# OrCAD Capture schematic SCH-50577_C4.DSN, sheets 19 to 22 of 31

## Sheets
19 21 USB: size C
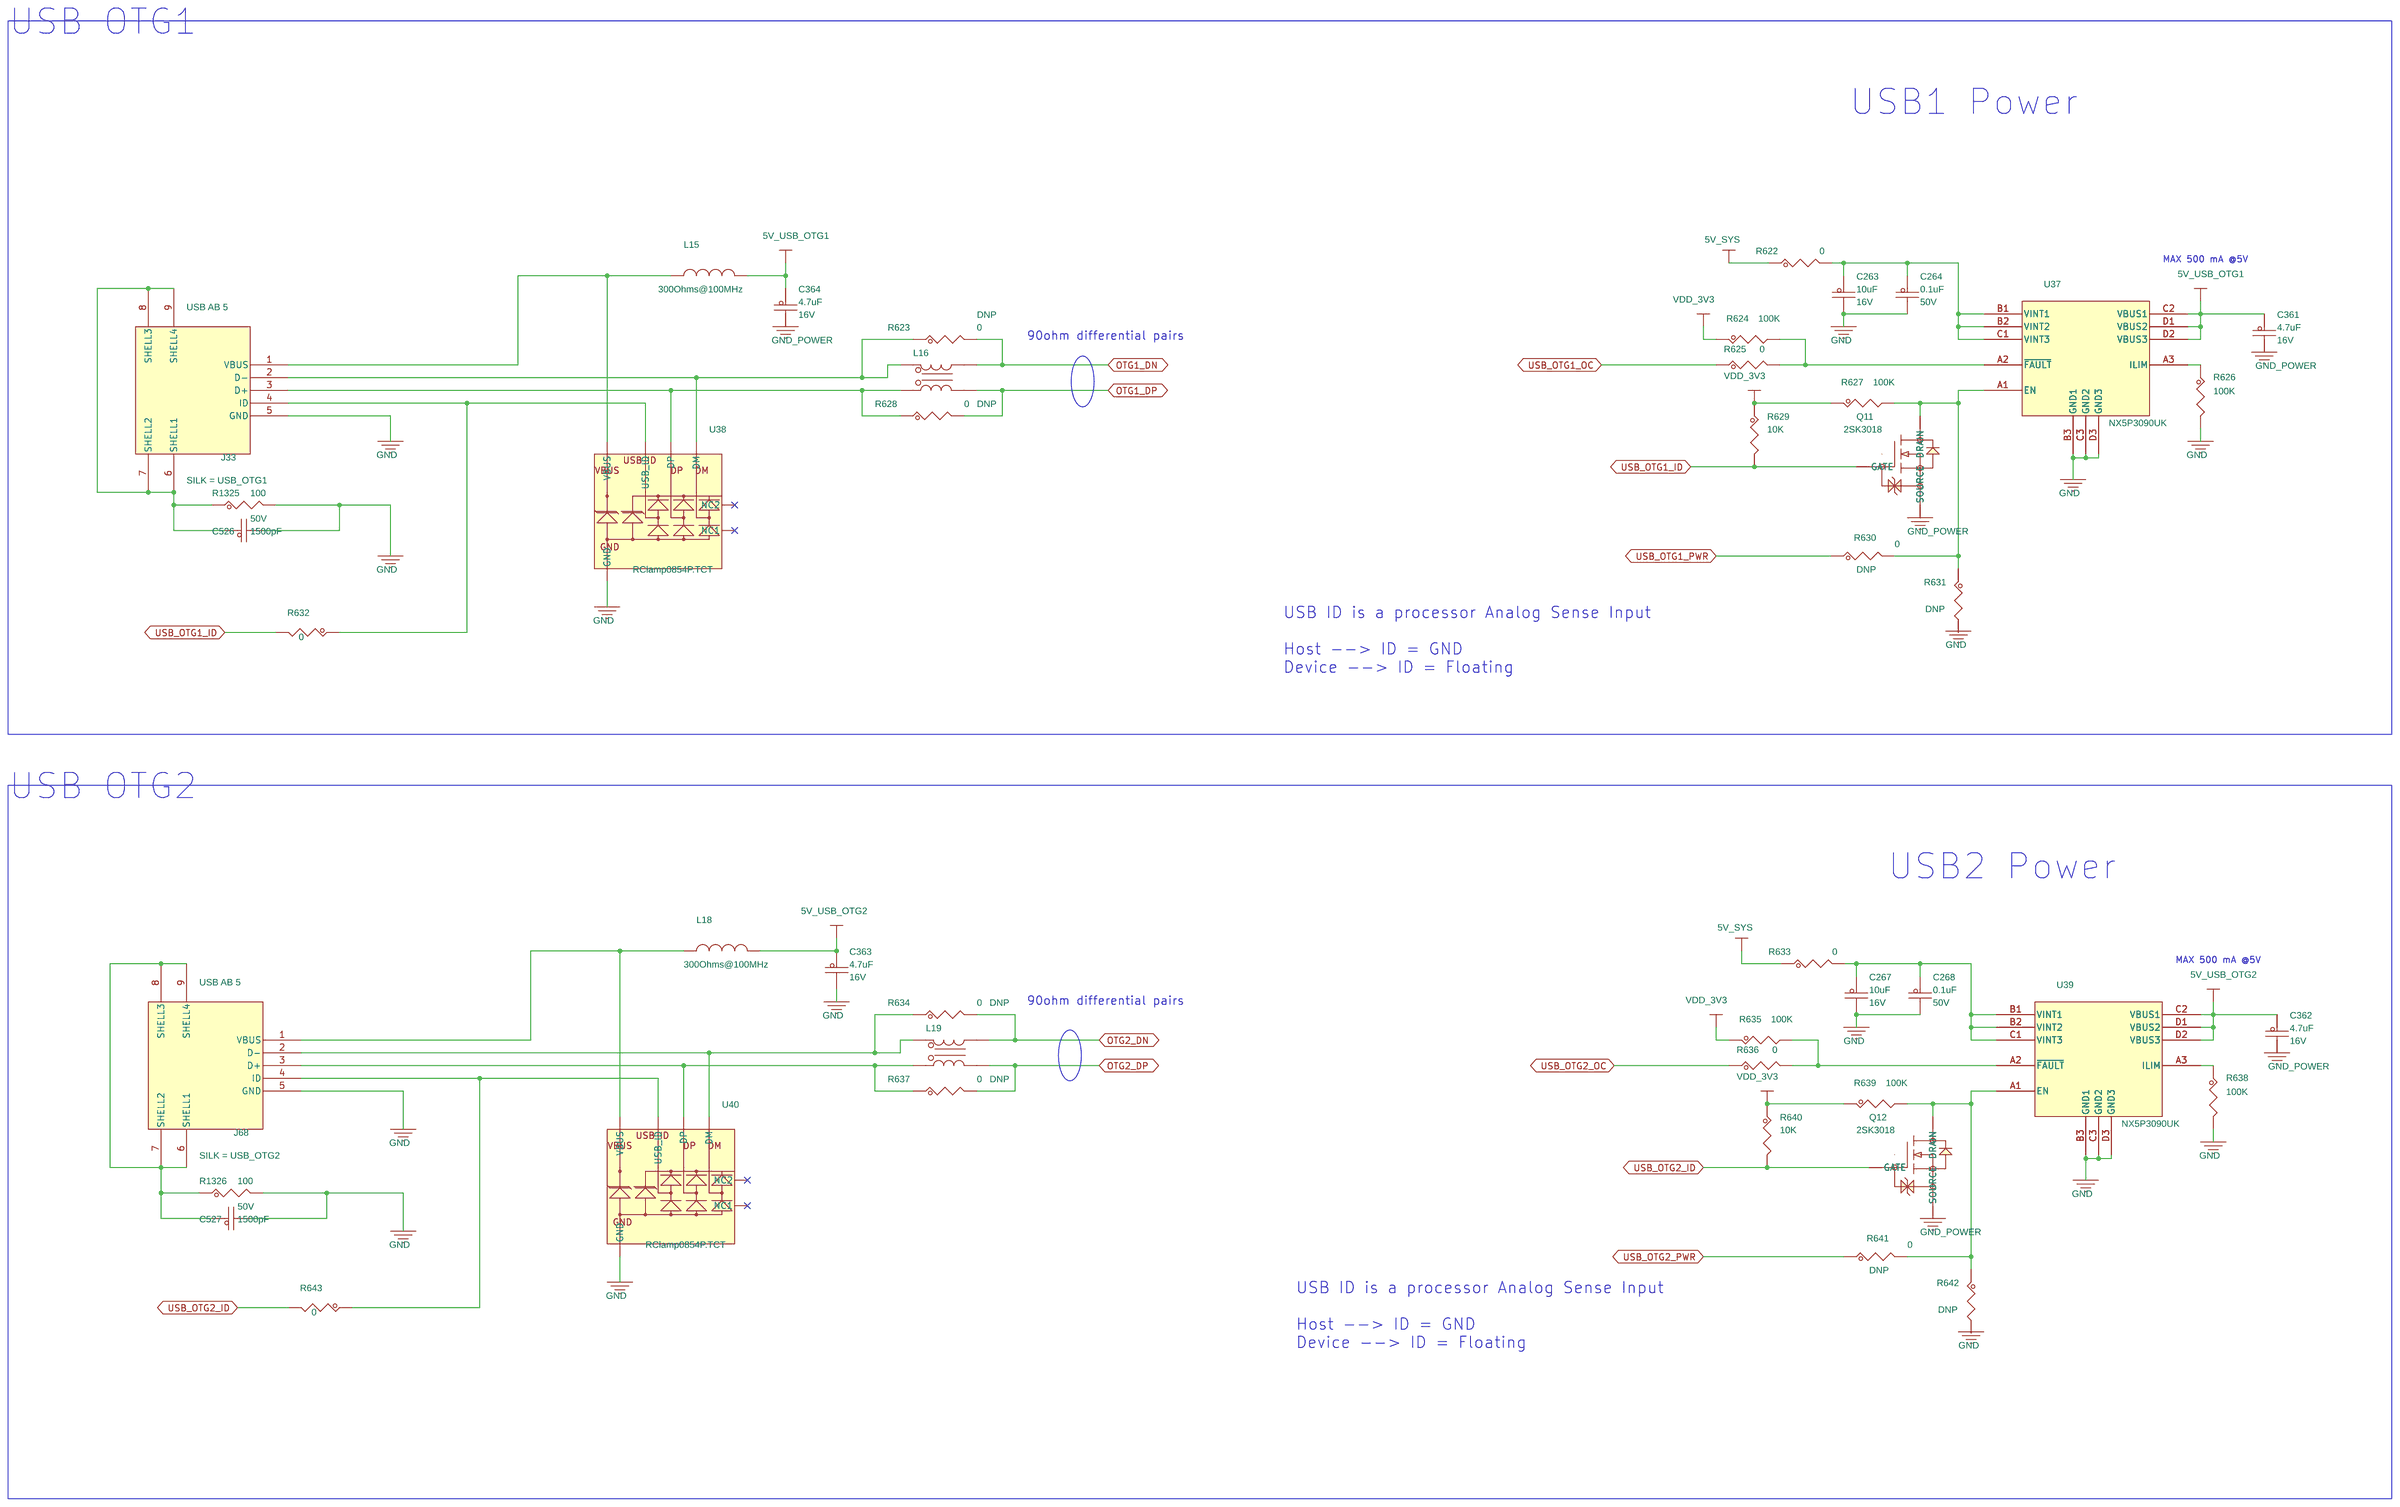
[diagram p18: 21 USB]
20 22 CAN: size C
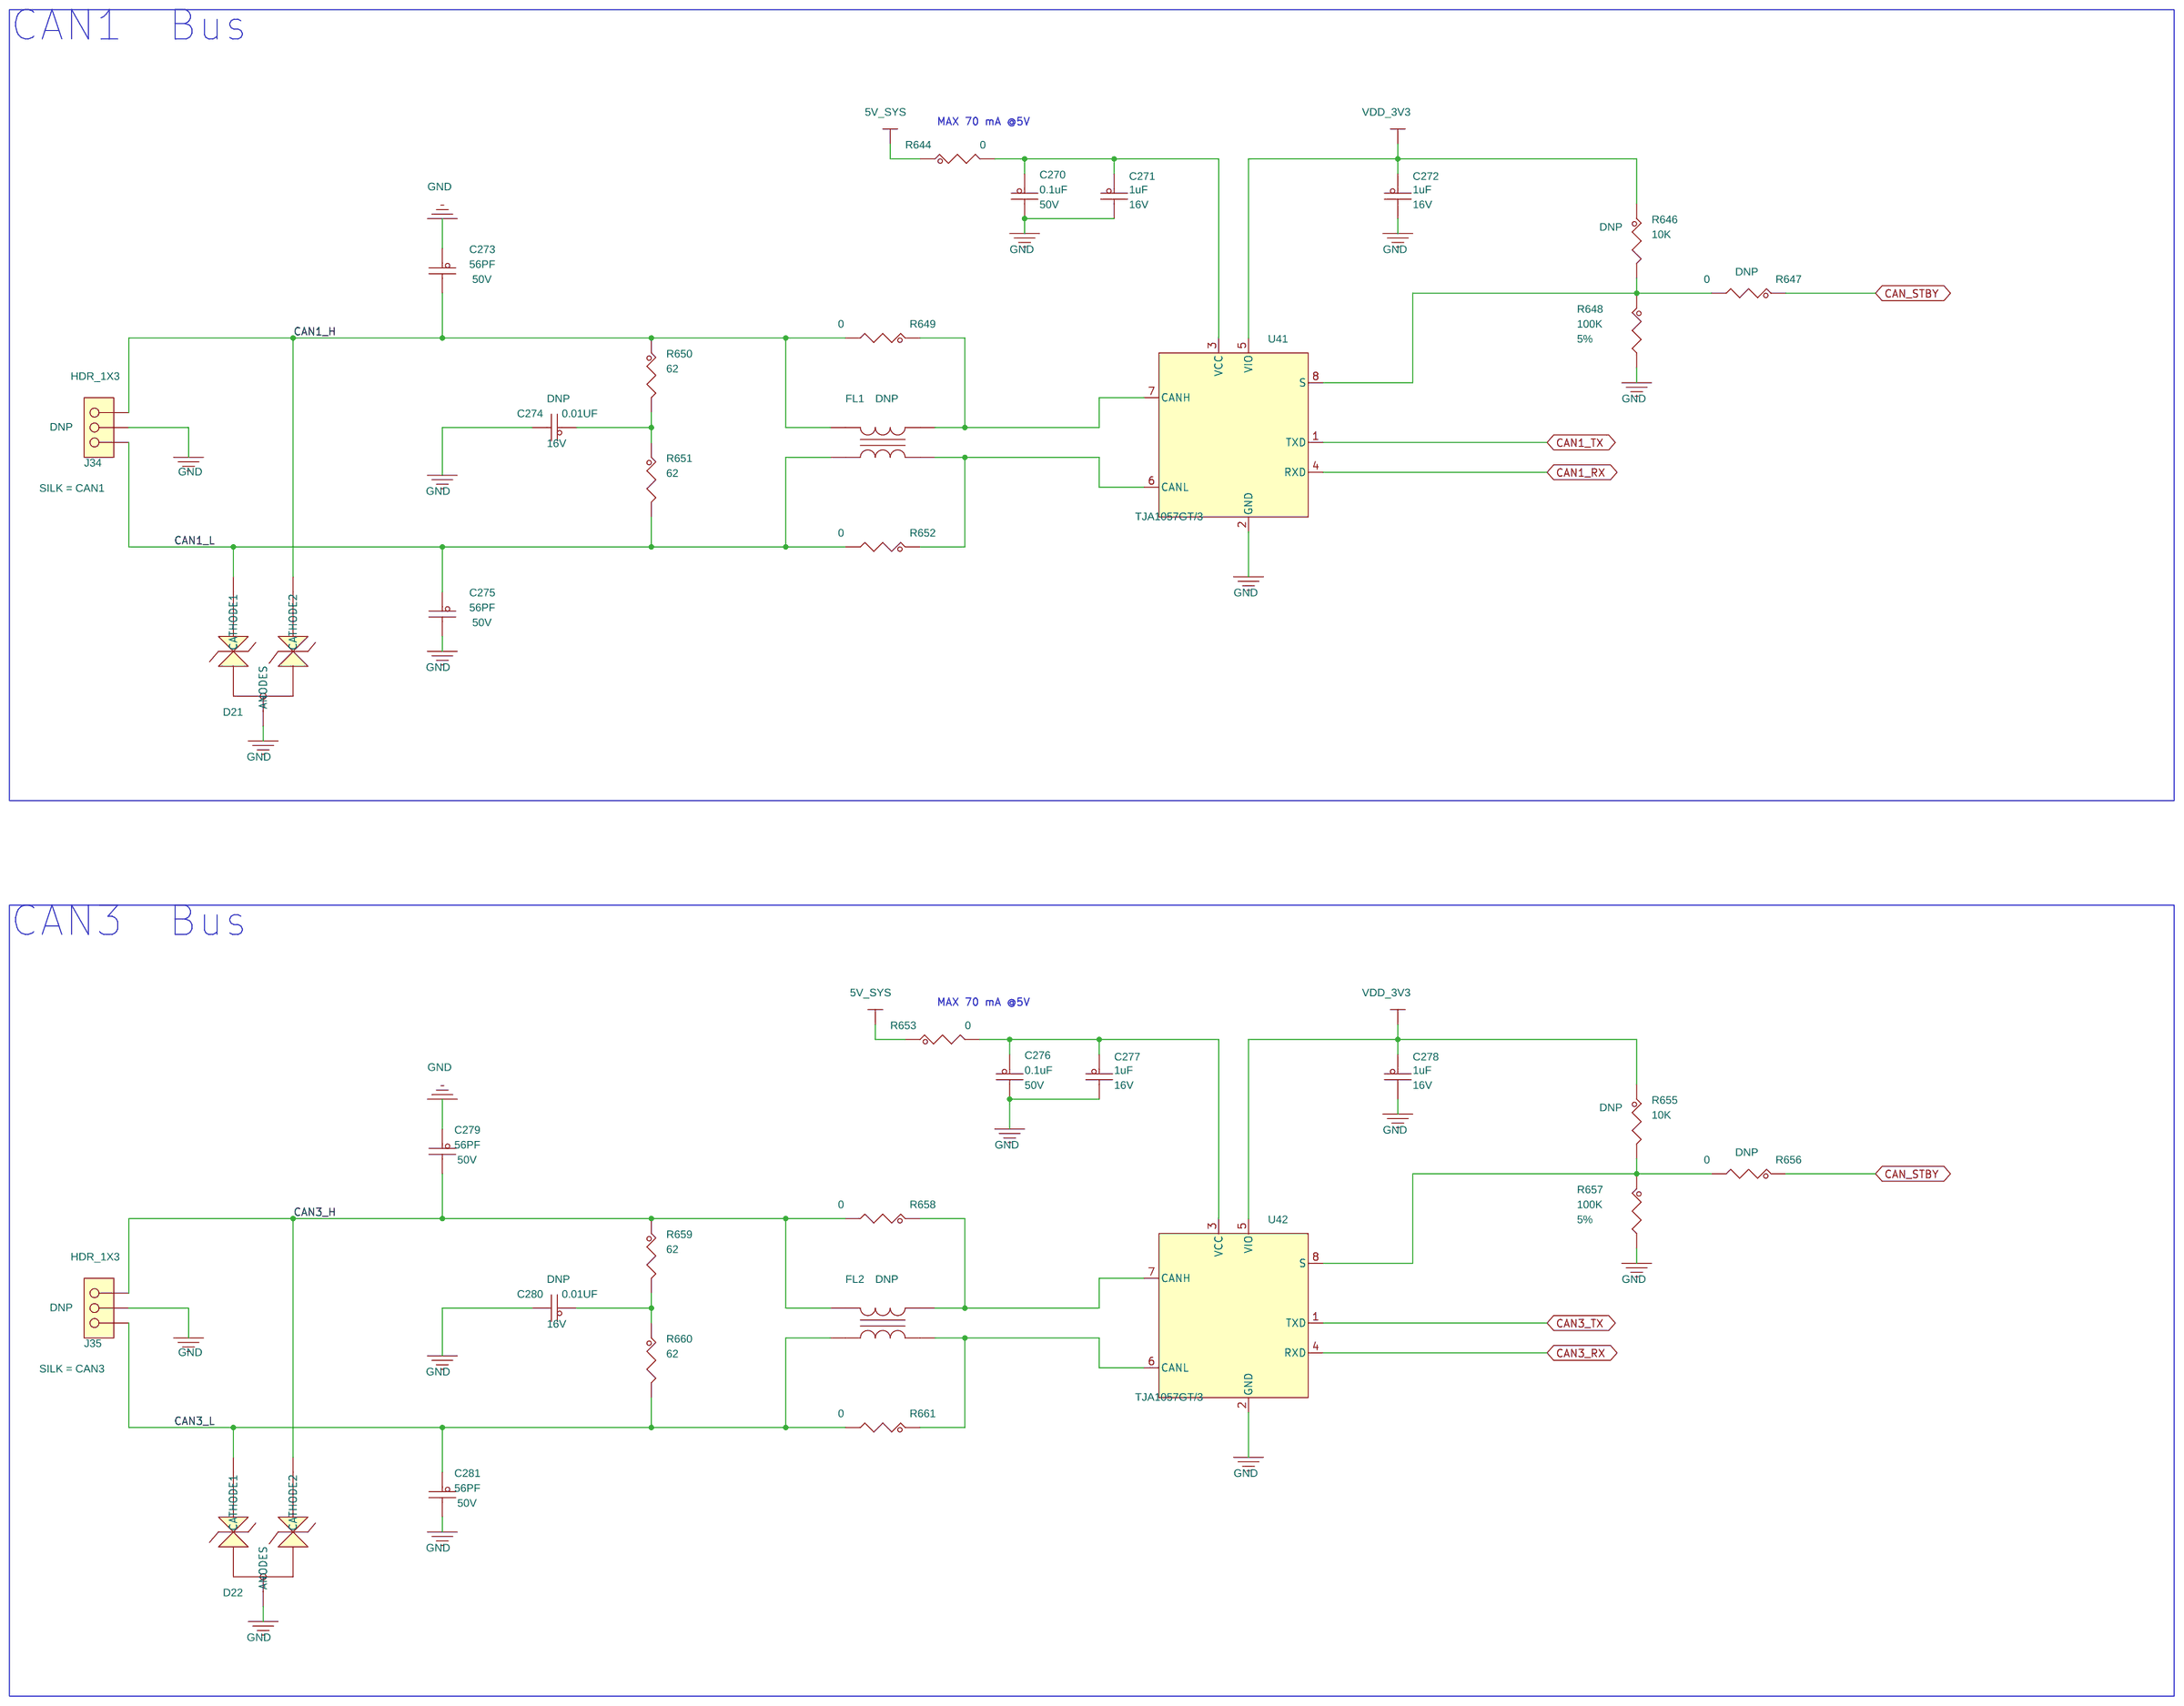
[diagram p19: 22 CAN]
21 23 M.2 Socket: size C
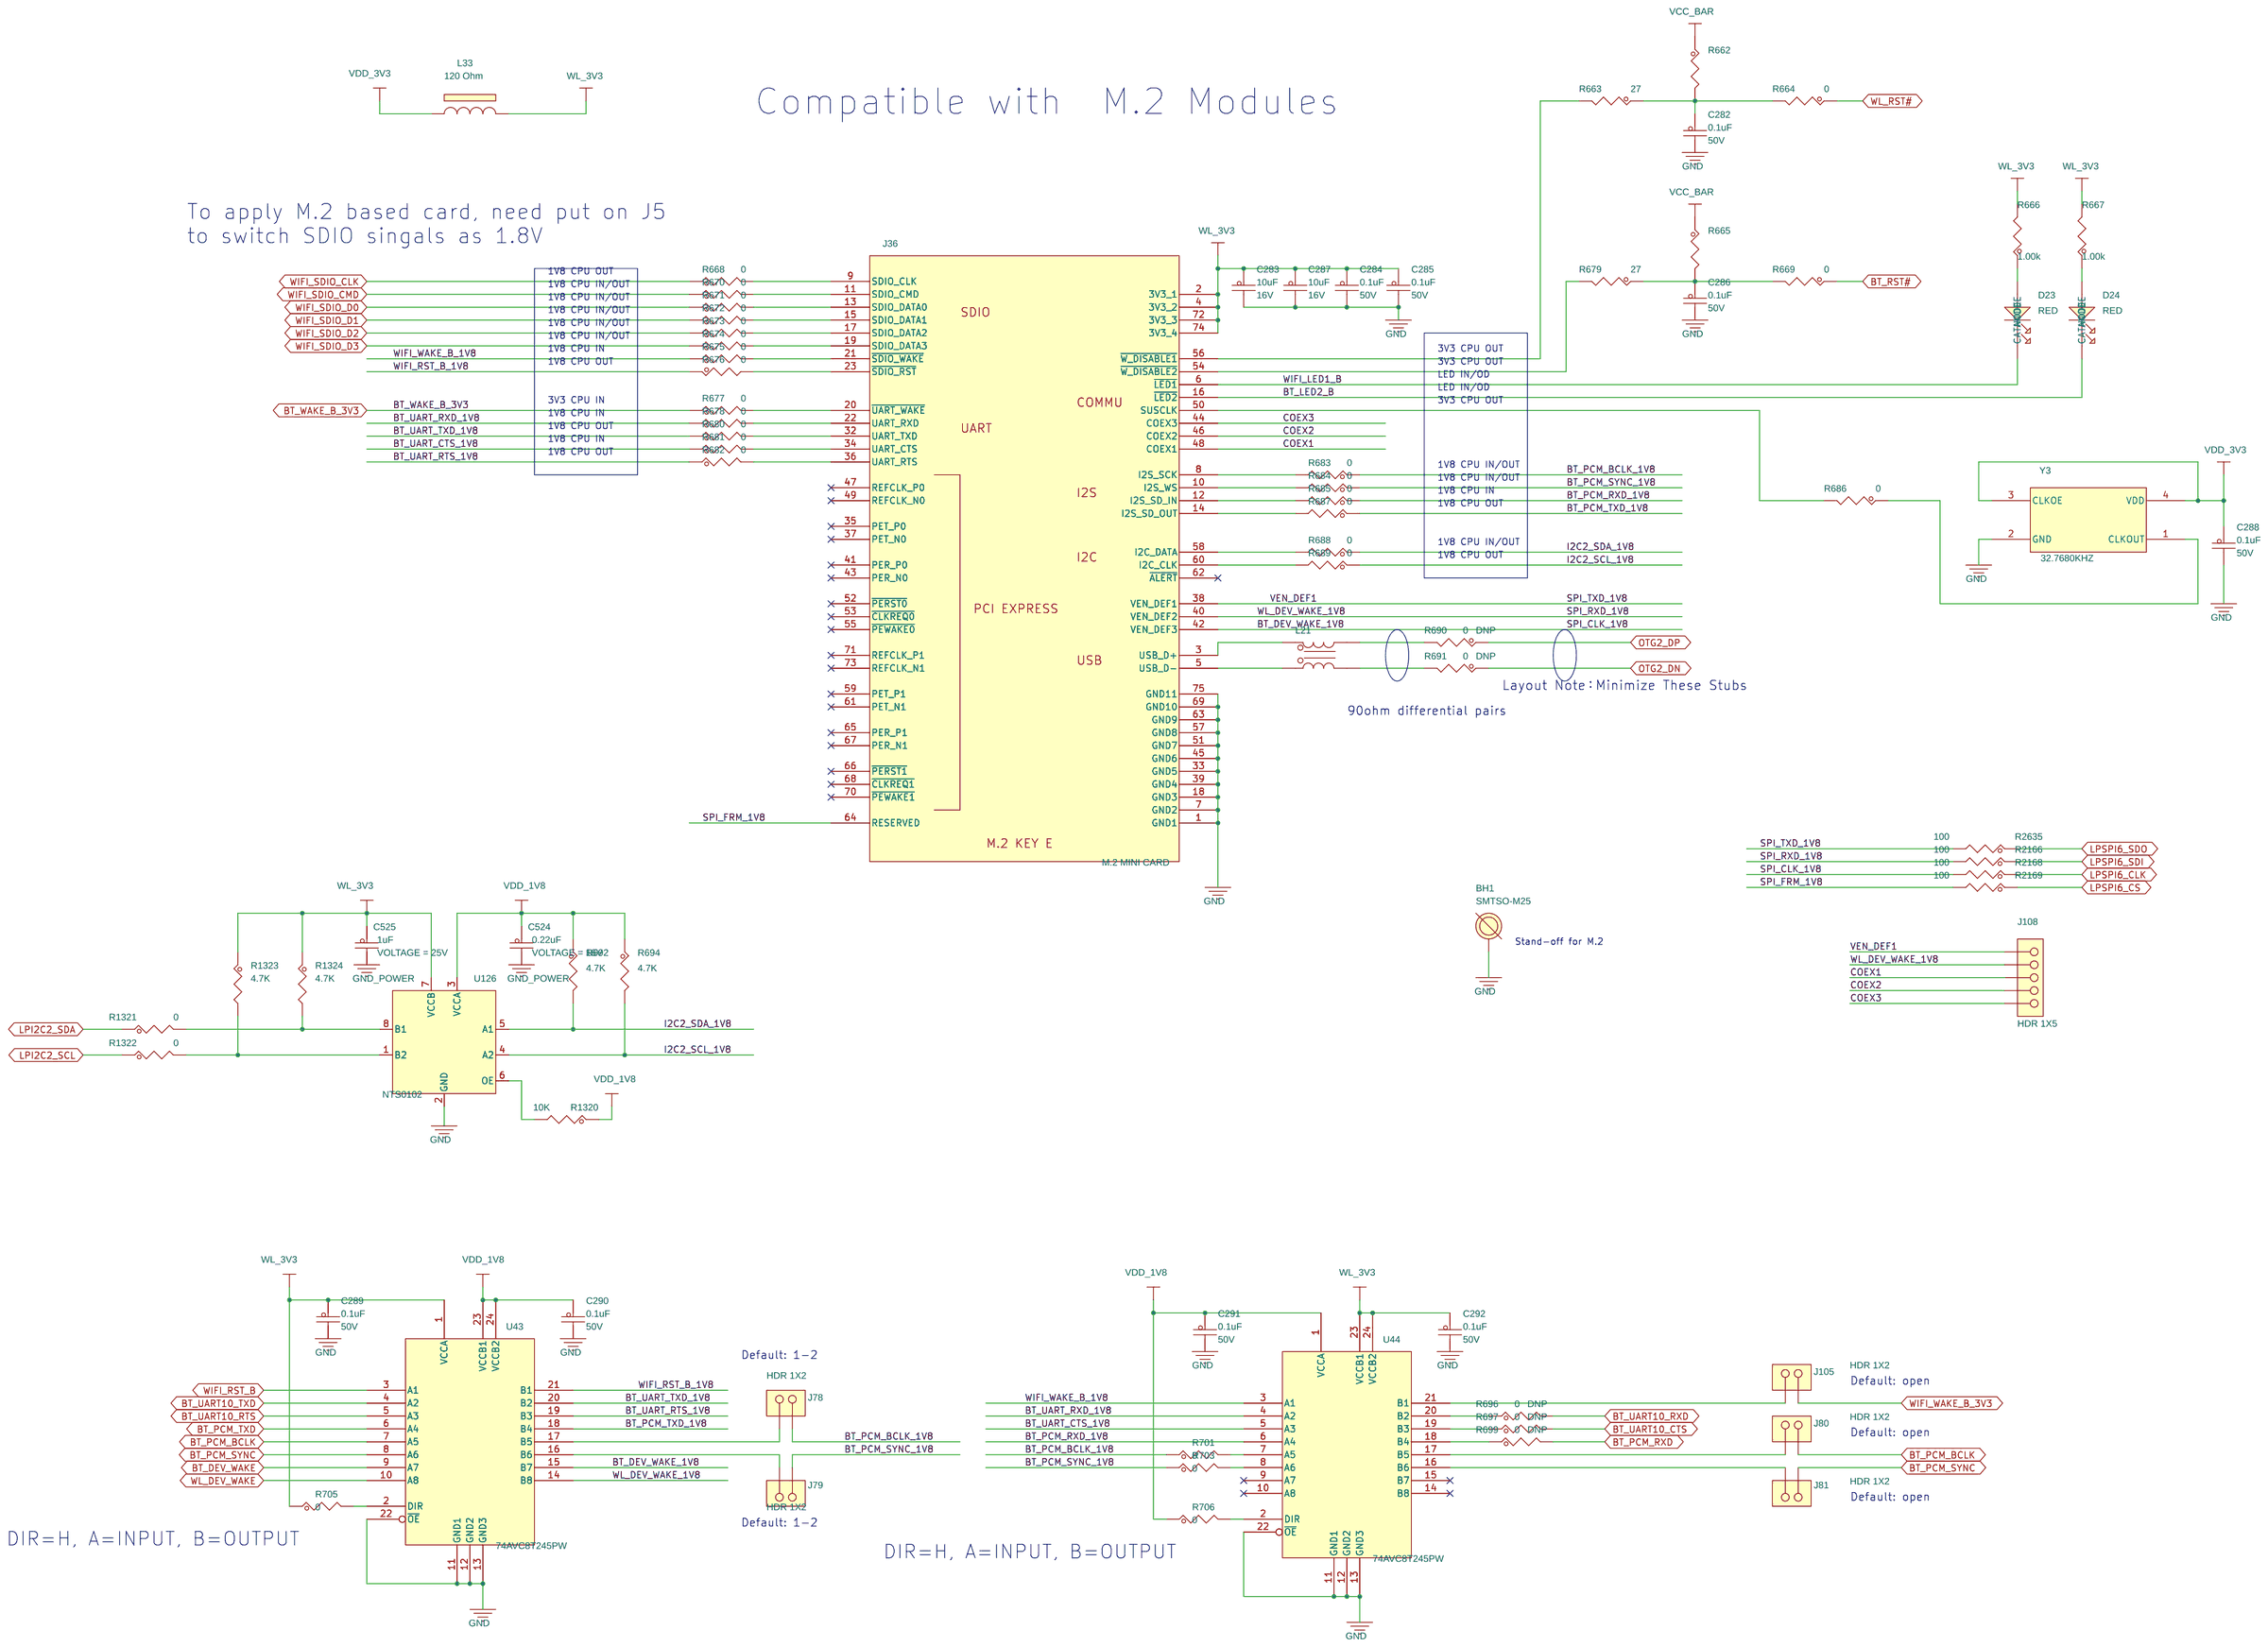
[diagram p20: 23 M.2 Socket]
22 24 Boot: size C
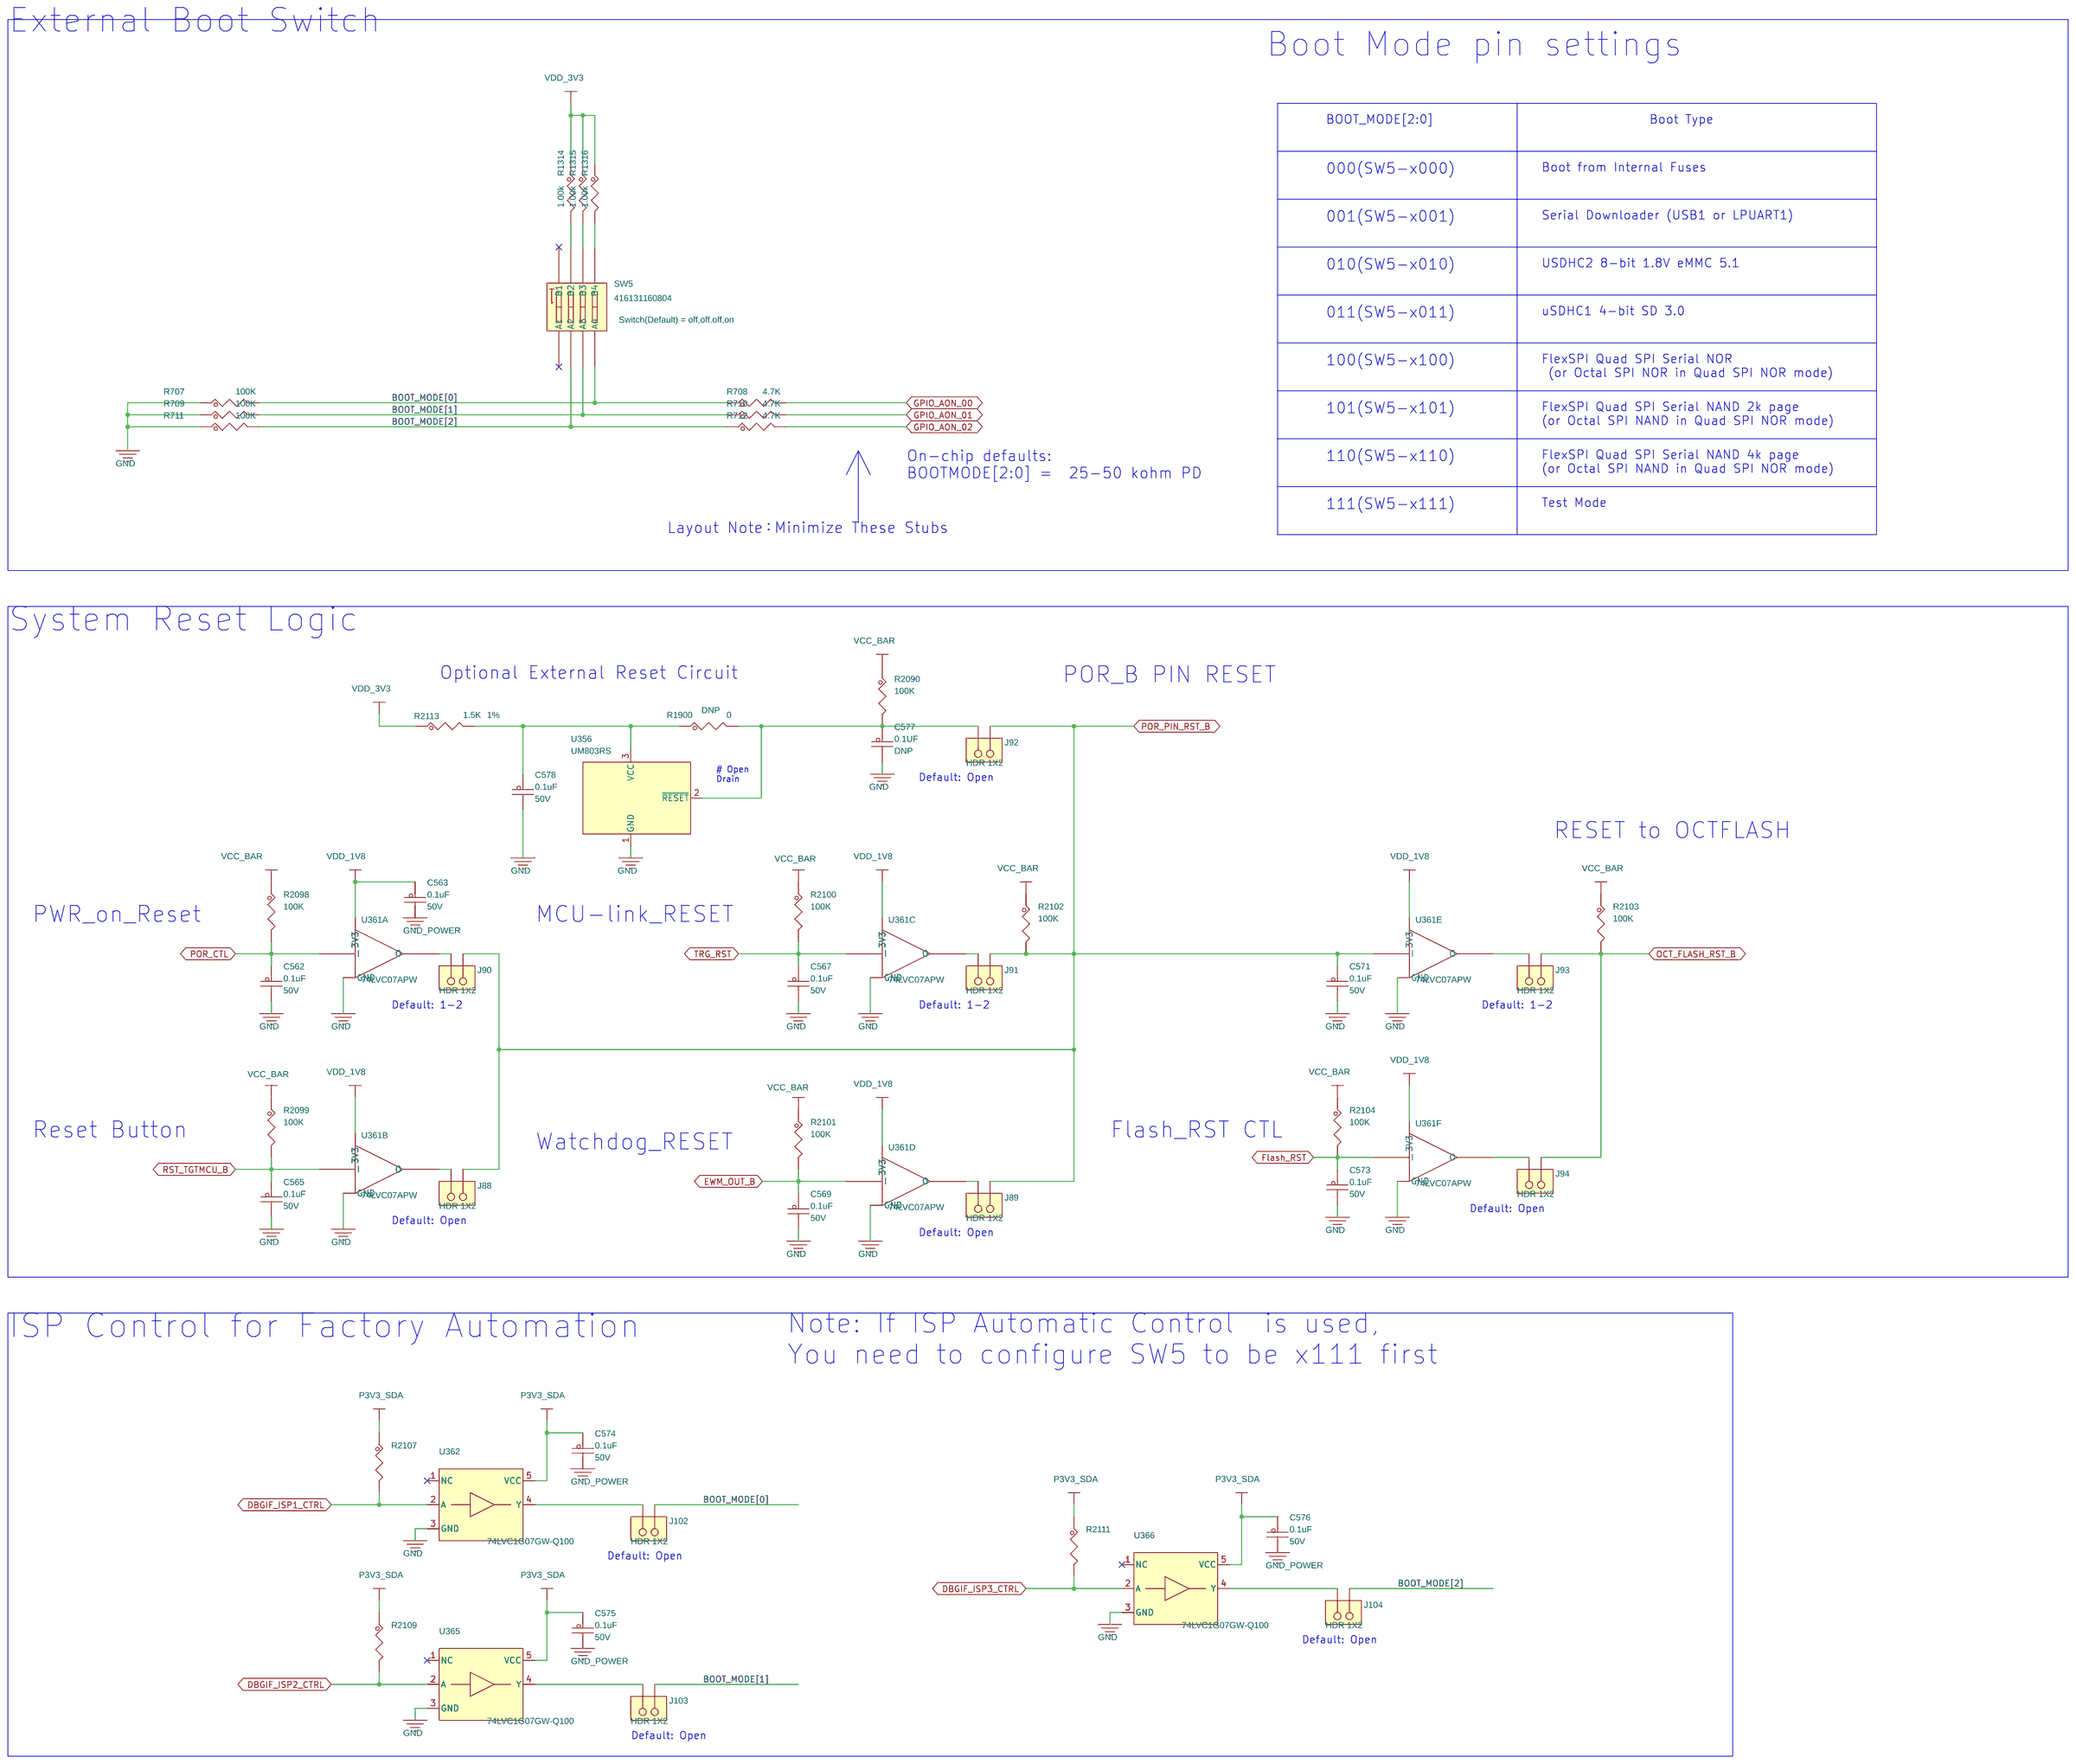
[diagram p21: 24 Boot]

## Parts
sheet 21 USB
C263  10uF  [CC0603_OV]
C264  0.1uF  [0402_CC]
C267  10uF  [CC0603_OV]
C268  0.1uF  [0402_CC]
C361  4.7uF  [CC0603_OV]
C362  4.7uF  [CC0603_OV]
C363  4.7uF  [CC0603_OV]
C364  4.7uF  [CC0603_OV]
C526  1500pF  [0402_CC]
C527  1500pF  [0402_CC]
J33  USB AB 5  [con9_microAB_usb_shell_th]
J68  USB AB 5  [con9_microAB_usb_shell_th]
L15  300Ohms@100MHz  [ind_1p8x1mm_sm]
L16  90OHM  [ind4_choke_0805]
L18  300Ohms@100MHz  [ind_1p8x1mm_sm]
L19  90OHM  [ind4_choke_0805]
Q11  2SK3018  [SOT323_3]
Q12  2SK3018  [SOT323_3]
R622  0  [0402_CC]
R623  0  [0402_CC]
R624  100K  [0402_CC]
R625  0  [0402_CC]
R626  100K  [0402_CC]
R627  100K  [0402_CC]
R628  0  [0402_CC]
R629  10K  [0402_CC]
R630  0  [0402_CC]
R631  10K  [0402_CC]
R632  0  [0402_CC]
R633  0  [0402_CC]
R634  0  [0402_CC]
R635  100K  [0402_CC]
R636  0  [0402_CC]
R637  0  [0402_CC]
R638  100K  [0402_CC]
R639  100K  [0402_CC]
R640  10K  [0402_CC]
R641  0  [0402_CC]
R642  10K  [0402_CC]
R643  0  [0402_CC]
R1325  100  [0402_CC]
R1326  100  [0402_CC]
U37  NX5P3090UK  [wlcsp12_0p4_1p38x1p68mm_smdp]
U38  RClamp0854P.TCT  [slp1616p6]
U39  NX5P3090UK  [wlcsp12_0p4_1p38x1p68mm_smdp]
U40  RClamp0854P.TCT  [slp1616p6]
sheet 22 CAN
C270  0.1uF  [0402_CC]
C271  1uF  [0402_CC]
C272  1uF  [0402_CC]
C273  56PF  [0402_CC]
C274  0.01UF  [0402_CC]
C275  56PF  [0402_CC]
C276  0.1uF  [0402_CC]
C277  1uF  [0402_CC]
C278  1uF  [0402_CC]
C279  56PF  [0402_CC]
C280  0.01UF  [0402_CC]
C281  56PF  [0402_CC]
D21  NUP2105L  [sot-23]
D22  NUP2105L  [sot-23]
FL1  ACT45B-510-2P  [ind4_4p7x3p4_smt]
FL2  ACT45B-510-2P  [ind4_4p7x3p4_smt]
J34  HDR_1X3  [HDR103]
J35  HDR_1X3  [HDR103]
R644  0  [0402_CC]
R646  10K  [0402_CC]
R647  0  [0402_CC]
R648  100K  [0402_CC]
R649  0  [0402_CC]
R650  62  [RC0805_OV]
R651  62  [RC0805_OV]
R652  0  [0402_CC]
R653  0  [0402_CC]
R655  10K  [0402_CC]
R656  0  [0402_CC]
R657  100K  [0402_CC]
R658  0  [0402_CC]
R659  62  [RC0805_OV]
R660  62  [RC0805_OV]
R661  0  [0402_CC]
U41  TJA1057GT/3  [SO8_1P27_4X5]
U42  TJA1057GT/3  [SO8_1P27_4X5]
sheet 23 M.2 Socket
BH1  SMTSO-M25  [mh244-166t]
C282  0.1uF  [0402_CC]
C283  10uF  [CC0603_OV]
C284  0.1uF  [0402_CC]
C285  0.1uF  [0402_CC]
C286  0.1uF  [0402_CC]
C287  10uF  [CC0603_OV]
C288  0.1uF  [0402_CC]
C289  0.1uF  [0402_CC]
C290  0.1uF  [0402_CC]
C291  0.1uF  [0402_CC]
C292  0.1uF  [0402_CC]
C524  0.22uF  [0402_CC]
C525  1uF  [cc0402_tol0p2]
D23  RED  [LED_0603]
D24  RED  [LED_0603]
J36  M.2 MINI CARD  [con_67_0p5_22x7p75_ra]
J78  HDR 1X2  [HDR102]
J79  HDR 1X2  [HDR102]
J80  HDR 1X2  [HDR102]
J81  HDR 1X2  [HDR102]
J105  HDR 1X2  [HDR102]
J108  HDR 1X5  [HDR105]
L21  90OHM  [ind4_choke_0805]
L33  120 Ohm  [0402_CC]
R662  10K  [0402_CC]
R663  27  [0402_CC]
R664  0  [0402_CC]
R665  10K  [0402_CC]
R666  1.00k  [0402_CC]
R667  1.00k  [0402_CC]
R668  0  [0402_CC]
R669  0  [0402_CC]
R670  0  [0402_CC]
R671  0  [0402_CC]
R672  0  [0402_CC]
R673  0  [0402_CC]
R674  0  [0402_CC]
R675  0  [0402_CC]
R676  0  [0402_CC]
R677  0  [0402_CC]
R678  0  [0402_CC]
R679  27  [0402_CC]
R680  0  [0402_CC]
R681  0  [0402_CC]
R682  0  [0402_CC]
R683  0  [0402_CC]
R684  0  [0402_CC]
R685  0  [0402_CC]
R686  0  [0402_CC]
R687  0  [0402_CC]
R688  0  [0402_CC]
R689  0  [0402_CC]
R690  0  [0402_CC]
R691  0  [0402_CC]
R692  4.7K  [0402_CC]
R694  4.7K  [0402_CC]
R696  0  [0402_CC]
R697  0  [0402_CC]
R699  0  [0402_CC]
R701  0  [0402_CC]
R703  0  [0402_CC]
R705  0  [0402_CC]
R706  0  [0402_CC]
R1320  10K  [0402_CC]
R1321  0  [0402_CC]
R1322  0  [0402_CC]
R1323  4.7K  [0402_CC]
R1324  4.7K  [0402_CC]
R2166  100  [0402_CC]
R2168  100  [0402_CC]
R2169  100  [0402_CC]
R2635  100  [0402_CC]
U43  74AVC8T245PW  [TSSOP24_65MM]
U44  74AVC8T245PW  [TSSOP24_65MM]
U126  NTS0102  [tssop8_a]
Y3  32.7680KHZ  [xtlosc4_3p3x1p6_sm]
sheet 24 Boot
C562  0.1uF  [CC0402_25]
C563  0.1uF  [CC0402_25]
C565  0.1uF  [CC0402_25]
C567  0.1uF  [CC0402_25]
C569  0.1uF  [CC0402_25]
C571  0.1uF  [CC0402_25]
C573  0.1uF  [CC0402_25]
C574  0.1uF  [0402_CC]
C575  0.1uF  [0402_CC]
C576  0.1uF  [0402_CC]
C577  0.1UF  [CC0402_25]
C578  0.1uF  [CC0402_25]
J88  HDR 1X2  [HDR102]
J89  HDR 1X2  [HDR102]
J90  HDR 1X2  [HDR102]
J91  HDR 1X2  [HDR102]
J92  HDR 1X2  [HDR102]
J93  HDR 1X2  [HDR102]
J94  HDR 1X2  [HDR102]
J102  HDR 1X2  [HDR102]
J103  HDR 1X2  [HDR102]
J104  HDR 1X2  [HDR102]
R707  100K  [0402_CC]
R708  4.7K  [0402_CC]
R709  100K  [0402_CC]
R710  4.7K  [0402_CC]
R711  100K  [0402_CC]
R712  4.7K  [0402_CC]
R1314  1.00k  [0402_CC]
R1315  1.00k  [0402_CC]
R1316  1.00k  [0402_CC]
R1900  0  [0402_CC]
R2090  100K  [0402_CC]
R2098  100K  [0402_CC]
R2099  100K  [0402_CC]
R2100  100K  [0402_CC]
R2101  100K  [0402_CC]
R2102  100K  [0402_CC]
R2103  100K  [0402_CC]
R2104  100K  [0402_CC]
R2107  10K  [0402_CC]
R2109  10K  [0402_CC]
R2111  10K  [0402_CC]
R2113  1.5K  [0402_CC]
SW5  416131160804  [sw4_dip_1p27_6p3x5p7]
U356  UM803RS  [sot-23]
U361  74LVC07APW  [TSSOP14]  (sections A,B,C,D,E,F)
U362  74LVC1G07GW-Q100  [sc70-5]
U365  74LVC1G07GW-Q100  [sc70-5]
U366  74LVC1G07GW-Q100  [sc70-5]

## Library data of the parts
C263 C267 C283 C287 = CAP_NP: CAP CER 10uF 16V 20% X6S AEC-Q200 0603; AGILE_PN: 150-80530; CAD_APPROVED: Yes; FPLIST: CC0603_OV,CC0603,0603_CC_NSP; HEIGHT: 1MM; MFG_NAME01: MURATA; MFG_PN01: GRT188C81C106ME13D; Package Size: 0603; ROHS: Yes; Temp Range: -55°C to 105°C; Tolerance: 10%; VOLTAGE: 16V
C264 C268 C270 C276 C282 C284-C286 C288-C292 C574-C576 = CAP_NP: CAP CER 0.1uF 50V 10% X7R AEC-Q200 0402; AGILE_PN: 150-79461; CAD_APPROVED: Yes; FPLIST: CC0402_25,CC0402_HD,0402_CC,CC0402_18,capc0402_l; HEIGHT: 0.55MM; MFG_NAME01: MURATA; MFG_PN01: GCM155R71H104KE02D; Package Size: 0402; ROHS: Yes; Tolerance: 10%; VOLTAGE: 50V
C361-C364 = CAP_NP: CAP CER 4.7uF 16V 10% X7R 0603; AGILE_PN: 150-80123; CAD_APPROVED: Yes; FPLIST: CC0603_OV,CC0603,0603_cc_tol,cc0603_0805_nsp; HEIGHT: 1MM; MFG_NAME01: MURATA; MFG_PN01: GRM188Z71C475KE21; Package Size: 0603; ROHS: Yes; Temp Range: -55°C ~ 125°C; Tolerance: 10%; VOLTAGE: 16V
C526 C527 = CAP_NP: CAP CER 1500PF 50V 10% X7R 0402; AGILE_PN: 150-76273; CAD_APPROVED: Yes; FPLIST: CC0402_25,CC0402_HD,0402_CC; HEIGHT: 0.55MM; MFG_NAME01: AVX; MFG_PN01: 04025C152KAT2A; ROHS: Yes; Tolerance: 10%; VOLTAGE: 50V
J33 = MICRO_USB_CONN_9PIN: CON 5 USB MICRO-AB RA SKT SMT 0.65MM SP AU; 3D_Mechanical_Footprint_File: ftp://fcl.am.freescale.net/ALLEGRO/step/con9_microAB_usb_shell_th.STEP; AGILE_PN: 211-78692; CAD_APPROVED: Yes; HEIGHT: 2.8MM; MFG_NAME01: HIROSE; MFG_PN01: ZX62D-AB-5P8(30); ROHS: Yes; SILK: USB_OTG1
J68 = MICRO_USB_CONN_9PIN: CON 5 USB MICRO-AB RA SKT SMT 0.65MM SP AU; 3D_Mechanical_Footprint_File: ftp://fcl.am.freescale.net/ALLEGRO/step/con9_microAB_usb_shell_th.STEP; AGILE_PN: 211-78692; CAD_APPROVED: Yes; HEIGHT: 2.8MM; MFG_NAME01: HIROSE; MFG_PN01: ZX62D-AB-5P8(30); ROHS: Yes; SILK: USB_OTG2
L15 L18 = INDUCTOR: IND FER BEAD 300Ohms@100MHz 2A 25% 0603; AGILE_PN: 180-78959; CAD_APPROVED: Yes; HEIGHT: 1MM; MFG_NAME01: WURTH ELEKTRONIK EISOS GMBH & CO. KG (ELECTRONIC & ELECTROMEHANICAL COMP); MFG_PN01: 742792641; Package Size: 0603; ROHS: Yes; Temp Range: -55°C to 125°C
L16 L19 L21 = DLW43: IND CHK 90 OHM@100MHZ 330MA 25% 0805; AGILE_PN: 180-76336; CAD_APPROVED: Yes; HEIGHT: 1MM; MFG_NAME01: MURATA; MFG_PN01: DLW21HN900SQ2L; PART_TYPE: CHOKE; ROHS: Yes; Temp Range: -40°C to +85°C; Temp_Range: -40°C to +85°C; Tolerance: 25%
Q11 Q12 = 2SK3018: TRANS MOSFET N-CH 30V .1A SOT-323; AGILE_PN: 480-75317; CAD_APPROVED: Yes; HEIGHT: 0.9MM; MFG_NAME01: ROHM; MFG_PN01: 2SK3018T106; ROHS: Yes
R622 R625 R632 R644 R649 R652 R653 R658 R661 R664 R668-R678 R680-R685 R687-R689 R701 R703 R705 R706 = RES: RES MF ZERO OHM 1/16W 5% 0402; AGILE_PN: 470-75394; CAD_APPROVED: Yes; FPLIST: RC0402_25,RC0402_HD,RC0402_X2,0402_CC; HEIGHT: 0.45 MM; MFG_NAME01: ROHM; MFG_PN01: MCR01MZPJ000; ROHS: Yes; Tolerance: 5%; VOLTAGE: 1/16W
R623 R628 R630 R647 R656 R690 R691 R696 R697 R699 R1900 = RES: RES MF ZERO OHM 1/16W 5% 0402; AGILE_PN: 470-75394; ASSY_OPT: DNP; CAD_APPROVED: Yes; FPLIST: RC0402_25,RC0402_HD,RC0402_X2,0402_CC; HEIGHT: 0.45 MM; MFG_NAME01: ROHM; MFG_PN01: MCR01MZPJ000; ROHS: Yes; Tolerance: 5%; VOLTAGE: 1/16W
R624 R627 R635 R639 R648 R657 = RES: RES MF 100K 1/16W 5% 0402; AGILE_PN: 470-75597; CAD_APPROVED: Yes; FPLIST: RC0402_25,RC0402_HD,0402_CC; HEIGHT: 0.40 MM; MFG_NAME01: VENKEL COMPANY; MFG_PN01: CR0402-16W-104JT; ROHS: Yes; TOL: 5%; Temp Range: -55C to +155C; Temp_Range: -55C to +155C; Tolerance: 5%; VOLTAGE: 50V
R626 R707 = RES: RES MF 100K 1/16W 1% 0402; AGILE_PN: 470-76240; CAD_APPROVED: Yes; FPLIST: RC0402_25,RC0402_HD,0402_CC; HEIGHT: 0.4MM; MFG_NAME01: NIC COMPONENTS CORP; MFG_PN01: NRCL04F1003TRF; ROHS: Yes; Tolerance: 1%
R629 R640 = RES: RES MF 10K 1/16W 5% 0402; AGILE_PN: 470-75557; CAD_APPROVED: Yes; FPLIST: RC0402_25,RC0402_HD,0402_CC; HEIGHT: 0.4 MM; MFG_NAME01: VISHAY INTERTECHNOLOGY; MFG_PN01: CRCW040210K0JNED; ROHS: Yes; Tolerance: 5%
R631 R642 R646 R655 = RES: RES MF 10K 1/16W 5% 0402; AGILE_PN: 470-75557; ASSY_OPT: DNP; CAD_APPROVED: Yes; FPLIST: RC0402_25,RC0402_HD,0402_CC; HEIGHT: 0.4 MM; MFG_NAME01: VISHAY INTERTECHNOLOGY; MFG_PN01: CRCW040210K0JNED; ROHS: Yes; Tolerance: 5%
R633 R636 R643 R686 R1321 R1322 = RES: RES MF ZERO OHM 1/16W 5% 0402; AGILE_PN: 470-75394; CAD_APPROVED: Yes; FPLIST: RC0402_25,RC0402_HD,RC0402_X2,0402_CC; HEIGHT: 0.45 MM; MFG_NAME01: YAGEO AMERICA; MFG_PN01: RC0402JR-070RL; ROHS: Yes; Tolerance: 5%; VOLTAGE: 1/16W
R634 R637 R641 = RES: RES MF ZERO OHM 1/16W 5% 0402; AGILE_PN: 470-75394; ASSY_OPT: DNP; CAD_APPROVED: Yes; FPLIST: RC0402_25,RC0402_HD,RC0402_X2,0402_CC; HEIGHT: 0.45 MM; MFG_NAME01: YAGEO AMERICA; MFG_PN01: RC0402JR-070RL; ROHS: Yes; Tolerance: 5%; VOLTAGE: 1/16W
R638 R709 R711 = RES: RES MF 100K 1/16W 1% 0402; AGILE_PN: 470-76240; CAD_APPROVED: Yes; FPLIST: RC0402_25,RC0402_HD,0402_CC; HEIGHT: 0.4MM; MFG_NAME01: VISHAY INTERTECHNOLOGY; MFG_PN01: CRCW0402100KFKEDC; ROHS: Yes; Tolerance: 1%
R1325 R1326 = RES: RES MF 100 OHM 1/16W 5% 0402; AGILE_PN: 470-75591; CAD_APPROVED: Yes; FPLIST: RC0402_25,RC0402_HD,RC0402_X2,0402_CC; HEIGHT: 0.45mm; MFG_NAME01: NIC COMPONENTS CORP; MFG_PN01: NRCL04J101TRF; ROHS: Yes; Tolerance: 5%
U37 U39 = NX5P3090UK_WLCSP12: IC USB PD TYPE C CURRENT LIMITED PWR SW 2.5-5.5V WLCSP12; AGILE_PN: 312-81574; CAD_APPROVED: Yes; HEIGHT: 0.565 MM; MFG_NAME01: NXP SEMICONDUCTORS; MFG_PN01: NX5P3090UK,012; ROHS: Yes
U38 U40 = RCLAMP1654P_NEW: DIODE TVS ARRAY 3 5.5V SLP1616P6; AGILE_PN: 480-78843; CAD_APPROVED: Yes; HEIGHT: 0.65MM; MFG_NAME01: SEMTECH CORP; ROHS: Yes; VOLTAGE: 5.5V
C271 C272 C277 C278 = CAP_NP: CAP CER 1.0uF 16V 10% X6S 0402; AGILE_PN: 150-80262; CAD_APPROVED: Yes; FPLIST: CC0402_25,CC0402_HD,0402_CC,capc0402_l; HEIGHT: 0.55MM; MFG_NAME01: MURATA; MFG_PN01: GRM155C81C105KE11D; ROHS: Yes; Temp Range: -55°C to +105°C; Tolerance: 10%; VOLTAGE: 16V
C273 C275 C279 C281 = CAP_NP: CAP CER 56PF 50V 5% C0G 0402; AGILE_PN: 150-30269; CAD_APPROVED: Yes; FPLIST: CC0402_25,CC0402_HD,0402_CC; HEIGHT: 0.55 MM; MFG_NAME01: VENKEL COMPANY; MFG_PN01: C0402C0G500-560JNE; ROHS: Yes; Tolerance: 5%; VOLTAGE: 50V
C274 C280 = CAP_NP: CAP CER 0.01UF 16V 20% X7R 0402; AGILE_PN: 150-30082; ASSY_OPT: DNP; CAD_APPROVED: Yes; FPLIST: CC0402_25,CC0402_HD,0402_CC; HEIGHT: 0.56MM; MFG_NAME01: AVX; MFG_PN01: 0402YC103MAT2A; Package Size: 0402; ROHS: Yes; TOL: 20%; Tolerance: 20%; VOLTAGE: 16V
D21 D22 = DIODE_NUP2105L: DIODE DUAL LINE CAN BUS PROTECTOR 27V 350W SOT-23; AGILE_PN: 480-77157; CAD_APPROVED: Yes; HEIGHT: 1.11MM; MFG_NAME01: On semiconductor; MFG_PN01: NUP2105LT1G; ROHS: Yes
FL1 FL2 = FILTER_4P: FILTER COMMON MODE 51uH@100kHZ 200mA 50V AEC-Q200 SMT; AGILE_PN: 180-77935; ASSY_OPT: DNP; CAD_APPROVED: Yes; HEIGHT: 3MM; MFG_NAME01: TDK; MFG_PN01: B82787C513H2; PART_TYPE: FILTER; ROHS: Yes
J34 = CONN_HDR_3X1: HDR 1X3 TH 100MIL SP 338H AU 98L; AGILE_PN: 210-81491; ASSY_OPT: DNP; CAD_APPROVED: Yes; HEIGHT: 8.59MM; MFG_NAME01: ANYTRONIC CORPORATION LIMITED; MFG_PN01: 0901S0203011N9T-31RF; ROHS: Yes; SILK: CAN1; Temp Range: -55°C to +105°C; Temp_Range: -55°C to +105°C
J35 = CONN_HDR_3X1: HDR 1X3 TH 100MIL SP 338H AU 98L; AGILE_PN: 210-81491; ASSY_OPT: DNP; CAD_APPROVED: Yes; HEIGHT: 8.59MM; MFG_NAME01: ANYTRONIC CORPORATION LIMITED; MFG_PN01: 0901S0203011N9T-31RF; ROHS: Yes; SILK: CAN3; Temp Range: -55°C to +105°C; Temp_Range: -55°C to +105°C
R650 R651 R659 R660 = RES: RES MF 62 OHM 1/8W 5% 0805; AGILE_PN: 470-30432; CAD_APPROVED: Yes; FPLIST: RC0805_OV,RC0805,0805_CC; HEIGHT: 0.7 MM; MFG_NAME01: BOURNS; MFG_PN01: CR0805-JW-620ELF; ROHS: Yes; Tolerance: 5%
U41 U42 = TJA1057GT3_8P: IC XCVR CAN 4.75-5.25V/2.95-5.25V AEC-Q100 SO8; AGILE_PN: 312-81479; CAD_APPROVED: Yes; HEIGHT: 1.75MM; MFG_NAME01: NXP SEMICONDUCTORS; ROHS: Yes; VOLTAGE: 4.75-5.25V/2.95-5.25V
BH1 = MOUNT_HOLE: FASTENER, STANDOFF M2.5-0.45 ROUND FEMALE OD CS L2MMX1MM; AGILE_PN: 280-77165; CAD_APPROVED: Yes; HEIGHT: 2.13MM; MFG_NAME01: SHENZHEN SINHOO SCIENCE TECHNOLOGY DEVELOPMENT CO.,LTD; MFG_PN01: NXP01-001; ROHS: Yes
C524 = CAP_NP: CAP CER 0.22uF 16V 10% X7R AEC-Q200 0402; AGILE_PN: 150-79207; CAD_APPROVED: Yes; FPLIST: CC0402_25,CC0402_HD,0402_CC,capc0402_l; HEIGHT: 0.55MM; MFG_NAME01: MURATA; MFG_PN01: GCM155R71C224KE02; Package Type: 0402; ROHS: Yes; Temp Range: -55°C to +125°C; Tolerance: 10%; VOLTAGE: 16V
C525 = CAP_NP: CAP CER 1uF 25V 10% X6S AEC-Q200 0402; AGILE_PN: 150-80570; CAD_APPROVED: Yes; FPLIST: cc0402_tol0p2,cc0402_tol0p2_ov,0402_cc_nsp; HEIGHT: 0.7MM; MFG_NAME01: MURATA; MFG_PN01: GRT155C81E105KE13D; Package Size: 1.1x0.6x0.6MM; Package Type: 0402; ROHS: Yes; Temp Range: -55°C to +105°C; Tolerance: 10%; VOLTAGE: 25V
D23 D24 = LED: LED RED SGL 20MA 0603; AGILE_PN: 370-76632; CAD_APPROVED: Yes; HEIGHT: 0.45MM; MFG_NAME01: LITE ON; MFG_PN01: LTST-C193KRKT-5A; ROHS: Yes
J36 = CON_67_FEMALE_RA: CON 67 M.2 NGFF MINI CARD DOUBLE SIDE RA SMT 0.5MM SP 165H AU; AGILE_PN: 211-80173; CAD_APPROVED: Yes; HEIGHT: 4.2 MM; MFG_NAME01: TE CONNECTIVITY LTD; MFG_PN01: 2199230-4; ROHS: Yes; Temp Range: -40C to 80C; Temp_Range: -40C to 80C
J78 J79 J90 J91 J93 = CONN_HDR_2X1: HDR 1X2 TH 100MIL SP 339H AU 98L; AGILE_PN: 210-81490; CAD_APPROVED: Yes; HEIGHT: 8.59MM; Jumper(Default): 1-2; MFG_NAME01: ANYTRONIC CORPORATION LIMITED; MFG_PN01: 0901S0202011N9T-31RF; ROHS: Yes; Temp_Range: -55°C to +105°C
J80 J81 J88 J89 J92 J94 J102-J105 = CONN_HDR_2X1: HDR 1X2 TH 100MIL SP 339H AU 98L; AGILE_PN: 210-81490; CAD_APPROVED: Yes; HEIGHT: 8.59MM; MFG_NAME01: ANYTRONIC CORPORATION LIMITED; MFG_PN01: 0901S0202011N9T-31RF; ROHS: Yes; Temp_Range: -55°C to +105°C
J108 = CONN_HDR_5X1: HDR 1X5 TH 100MIL SP 346H SN 118L; 3D_Mechanical_Footprint_File: ftp://fcl.am.freescale.net/ALLEGRO/step/hdr105.STEP; AGILE_PN: 210-79555; CAD_APPROVED: Yes; HEIGHT: 8.79MM; MFG_NAME01: GREENCONN CORPORATION; MFG_PN01: GPHA114-0501A01; ROHS: Yes
L33 = INDUCTOR_FERRITE: IND FER BEAD 120 OHM@100MHZ 0.5A 25% 0402; AGILE_PN: 180-77771; CAD_APPROVED: Yes; FPLIST: IND_0402,0402_CC; HEIGHT: 0.55MM; MFG_NAME01: MURATA; MFG_PN01: BLM15AG121SN1D; PART_TYPE: FERRITE\BEAD; Package Size: 0402; ROHS: Yes; Tolerance: 25%
R662 R665 R2107 R2109 R2111 = RES: RES MF 10K 1/16W 5% 0402; AGILE_PN: 470-75557; CAD_APPROVED: Yes; FPLIST: RC0402_25,RC0402_HD,0402_CC; HEIGHT: 0.4 MM; MFG_NAME01: VISHAY INTERTECHNOLOGY; MFG_PN01: CRCW040210K0JNED; ROHS: Yes; TOL: 5%; Tolerance: 5%
R663 R679 = RES: RES MF 27 OHM 1/16W 5% AEC-Q200 0402; AGILE_PN: 470-80519; CAD_APPROVED: Yes; FPLIST: RC0402_25,RC0402_HD,0402_CC; HEIGHT: 0.4 MM; MFG_NAME01: VISHAY INTERTECHNOLOGY; MFG_PN01: CRCW040227R0JNED; ROHS: Yes; Tolerance: 5%
R666 R667 = RES: RES MF 1.00k Ohm 1/16W 1% AEC-Q200 0402; AGILE_PN: 470-80511; CAD_APPROVED: Yes; EN: 101-1-00293; FPLIST: RC0402_25,RC0402_HD,0402_CC; HEIGHT: 0.4 MM; MFG_NAME01: KOA SPEER; MFG_PN01: RK73H1ETTP1001F; ROHS: Yes; TOL: 1%; Tolerance: 1%
R692 R694 R1323 R1324 = RES: RES MF 4.7K 1/16W 5% 0402; AGILE_PN: 470-75626; CAD_APPROVED: Yes; FPLIST: RC0402_25,RC0402_HD,0402_CC; HEIGHT: 0.41mm; MFG_NAME01: NIC COMPONENTS CORP; MFG_PN01: NRCL04J472TRF; ROHS: Yes; Tolerance: 5%
R1320 = RES: RES MF 10K OHM 5% 1/10W AEC-Q200 0402; AGILE_PN: 470-81195; CAD_APPROVED: Yes; FPLIST: RC0402_25,RC0402_HD,0402_CC; HEIGHT: 0.4 MM; MFG_NAME01: PANASONIC; MFG_PN01: ERJ-2GEJ103X; ROHS: Yes
R2166 R2168 R2169 R2635 = RES: RES MF 100 OHM 1/16W 5% AEC-Q200 0402; AGILE_PN: 470-80555; CAD_APPROVED: Yes; FPLIST: RC0402_25,RC0402_HD,RC0402_X2,0402_CC; HEIGHT: 0.45mm; MFG_NAME01: VISHAY INTERTECHNOLOGY; MFG_PN01: CRCW0402100RJNED; ROHS: Yes
U43 U44 = SN74AVC8T245: IC VXLTR 8BIT TS 1.2-3.6V TSSOP-24; AGILE_PN: 312-79594; CAD_APPROVED: Yes; HEIGHT: 1.2MM; MFG_NAME01: NEXPERIA; MFG_PN01: 74AVC8T245PW,118; ROHS: Yes; VOLTAGE: 1.4V-3.6V
U126 = NTB0102_8P: IC XCVR 2-BIT 1.65-3.6V/2.3-5.5V TSSOP8; AGILE_PN: 312-80889; CAD_APPROVED: Yes; HEIGHT: 1.1MM; MFG_NAME01: NXP SEMICONDUCTORS; MFG_PN01: NTS0102DP; ROHS: Yes; VOLTAGE: 1.65-3.6V/2.3-5.5V
Y3 = OSC_4P: OSC 32.7680KHZ FIXED 1.2-5.5V SMT; AGILE_PN: 230-77232; CAD_APPROVED: Yes; HEIGHT: 1.0MM; MFG_NAME01: GOLLEDGE ELECTRONICS LTD; MFG_PN01: OV7604C7; ROHS: Yes
C562 C563 C565 C567 C569 C571 C573 C578 = CAP_NP: CAP CER 0.1uF 50V 10% X7R AEC-Q200 0402; AGILE_PN: 150-79461; CAD_APPROVED: Yes; FPLIST: CC0402_25,CC0402_HD,0402_CC,CC0402_18,capc0402_l; HEIGHT: 0.55MM; MFG_NAME01: MURATA; MFG_PN01: GCM155R71H104KE02D; Package Size: 0402; ROHS: Yes; Rated Voltage: 50V; Temp Range: -55C to +125C; Tolerance: 10%
C577 = CAP_NP: CAP CER 0.1UF 10V 10% X5R 0402; AGILE_PN: 150-75634; ASSY_OPT: DNP; CAD_APPROVED: Yes; FPLIST: CC0402_25,CC0402_HD,0402_CC; HEIGHT: 0.64MM; MFG_NAME01: YAGEO AMERICA; MFG_PN01: CC0402KRX5R6BB104; Package Size: 0402; ROHS: Yes; Tolerance: 10%; VOLTAGE: 10V
R708 R710 R712 = RES: RES MF 4.7K 1/16W 5% 0402; AGILE_PN: 470-75626; CAD_APPROVED: Yes; FPLIST: RC0402_25,RC0402_HD,0402_CC,RC0402_X2; HEIGHT: 0.41mm; MFG_NAME01: NIC COMPONENTS CORP; MFG_PN01: NRCL04J472TRF; ROHS: Yes; Tolerance: 5%
R1314-R1316 = RES: RES MF 1.00k Ohm 1/16W 1% AEC-Q200 0402; AGILE_PN: 470-80511; CAD_APPROVED: Yes; FPLIST: RC0402_25,RC0402_HD,0402_CC; HEIGHT: 0.4 MM; MFG_NAME01: KOA SPEER; MFG_PN01: RK73H1ETTP1001F; ROHS: Yes; Tolerance: 1%
R2090 R2098-R2104 = RES: RES MF 100K 1/16W 5% 0402; AGILE_PN: 470-75597; CAD_APPROVED: Yes; FPLIST: RC0402_25,RC0402_HD,0402_CC; HEIGHT: 0.40 MM; MFG_NAME01: VENKEL COMPANY; MFG_PN01: CR0402-16W-104JT; ROHS: Yes; Temp Range: -55C to +155C; Temp_Range: -55C to +155C; Tolerance: 5%; VOLTAGE: 50V
R2113 = RES: RES MF 1.5K 1/16W 1% 0402; AGILE_PN: 470-80487; CAD_APPROVED: Yes; FPLIST: RC0402_25,RC0402_HD,0402_CC; HEIGHT: 0.4MM; MFG_NAME01: BOURNS; MFG_PN01: CR0402-FX-1501GLF; ROHS: Yes; Tolerance: 1%
SW5 = SW_DIP4: SW DIP 4 POS 0.025A@24VDC SMT; AGILE_PN: 510-78047; CAD_APPROVED: Yes; HEIGHT: 2.1MM; MFG_NAME01: WURTH ELEKTRONIK EISOS GMBH & CO. KG (ELECTRONIC & ELECTROMEHANICAL COMP); ROHS: Yes; Switch(Default): off,off.off,on
U356 = SGM803_SOT23-3P: IC VOLT MONITOR 2.63V RST VTH 1-5.5V AUTO SOT-23; AGILE_PN: 315-80553; CAD_APPROVED: Yes; HEIGHT: 1.25MM; MFG_NAME01: UNION SEMICONDUCTOR, INC; ROHS: Yes; VOLTAGE: 1-5.5V
U361 = 74LVC07APW: IC BUF HEX 1.65-5.5V TSSOP14; 3D_Mechanical_Footprint_File: ftp://fcl.am.freescale.net/ALLEGRO/step/tssop14.STEP; AGILE_PN: 312-75315; HEIGHT: 1.1mm; MFG_NAME01: Nexperia; ROHS: No; Temp Range: -40°C to +125°C; VOLTAGE: 1.65-5.5V
U362 U365 U366 = 74AUP1G07GW: IC BUF NON-INV SGL 1.65-5.5V AEC-Q100 TSSOP5; 3D_Mechanical_Footprint_File: ftp://fcl.am.freescale.net/ALLEGRO/step/sc70-5.STEP; AGILE_PN: 312-82179; CAD_APPROVED: Yes; HEIGHT: 1.1MM; MFG_NAME01: NEXPERIA; MFG_PN01: 74LVC1G07GW-Q100H; ROHS: Yes; Temp Range: -40 to +125C; VOLTAGE: 1.65-5.5V

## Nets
5V_SYS: R622.1 R633.1 R644.1 R653.1 ; also on sheet 5 6 14 24 25 26 27 29
5V_USB_OTG1: C361.1 C364.1 L15.2 U37.C2(VBUS1) U37.D1(VBUS2) U37.D2(VBUS3) ; also on sheet 5 9
5V_USB_OTG2: C362.1 C363.1 L18.2 U39.C2(VBUS1) U39.D1(VBUS2) U39.D2(VBUS3) ; also on sheet 5 9
GND: BH1.1 C263.2 C264.2 C267.2 C268.2 C270.2 C271.2 C272.2 C273.1 C274.2 C275.2 C276.2 C277.2 C278.2 C279.1 C280.2 C281.2 C282.2 C283.2 C284.2 C285.2 C286.2 C287.2 C288.2 C289.2 C290.2 C291.2 C292.2 C361.2 C362.2 C363.2 C364.2 C524.2 C525.2 C526.2 C527.2 C562.2 C563.2 C565.2 C567.2 C569.2 C571.2 C573.2 C574.2 C575.2 C576.2 C577.2 C578.2 D21.3(ANODES) D22.3(ANODES) J33.5(GND) J34.2 J35.2 J36.1(GND1) J36.7(GND2) J36.18(GND3) J36.33(GND5) J36.39(GND4) J36.45(GND6) J36.51(GND7) J36.57(GND8) J36.63(GND9) J36.69(GND10) J36.75(GND11) J68.5(GND) Q11.1(SOURCE) Q12.1(SOURCE) R626.2 R631.2 R638.2 R642.2 R648.2 R657.2 R707.1 R709.1 R711.1 R1325.2 R1326.2 U37.B3(GND1) U37.C3(GND2) U37.D3(GND3) U38.7(GND) U39.B3(GND1) U39.C3(GND2) U39.D3(GND3) U40.7(GND) U41.2(GND) U42.2(GND) U43.11(GND1) U43.12(GND2) U43.13(GND3) U43.22(~{OE}) U44.11(GND1) U44.12(GND2) U44.13(GND3) U44.22(~{OE}) U126.2(GND) U356.1(GND) U361.7(GND) U362.3(GND) U365.3(GND) U366.3(GND) Y3.2(GND) ; also on sheet 2 5 6 7 8 9 10 11 12 13 14 15 16 17 18 23 24 25 26 27 28 29 30 31
P3V3_SDA: C574.1 C575.1 C576.1 R2107.1 R2109.1 R2111.1 U362.5(VCC) U365.5(VCC) U366.5(VCC) ; also on sheet 23
VDD_1V8: C290.1 C291.1 C524.1 C563.1 R692.1 R694.1 R706.1 R1320.1 R2090.1 R2102.1 U43.23(VCCB1) U43.24(VCCB2) U44.1(VCCA) U126.3(VCCA) U361.14(3V3) ; also on sheet 6 7 8 9 14 16 24
VDD_BBSM_3V3: R2098.1 ; also on sheet 5 6 7
BOOT_MODE[0]: J102.2 R707.2 R708.1 SW5.4(A4)
BOOT_MODE[1]: J103.2 R709.2 R710.1 SW5.3(A3)
BOOT_MODE[2]: J104.2 R711.2 R712.1 SW5.2(A2)
BT_DEV_WAKE: U43.9(A7) ; also on sheet 8
BT_DEV_WAKE_1V8: J36.42(VEN_DEF3) R2168.2 U43.15(B7)
BT_LED2_B: D24.C(CATHODE) J36.16(~{LED2})
BT_PCM_BCLK: J80.2 U43.7(A5) ; also on sheet 8
BT_PCM_BCLK_1V8: J78.2 R683.1 R701.1
BT_PCM_RXD: R699.2 ; also on sheet 8
BT_PCM_RXD_1V8: R685.1 U44.6(A4)
BT_PCM_SYNC: J81.2 U43.8(A6) ; also on sheet 8
BT_PCM_SYNC_1V8: J79.2 R684.1 R703.1
BT_PCM_TXD: U43.6(A4) ; also on sheet 8
BT_PCM_TXD_1V8: R687.1 U43.18(B4)
BT_RST#: R669.1 ; also on sheet 8
BT_UART10_CTS: R697.2 ; also on sheet 8
BT_UART10_RTS: U43.5(A3) ; also on sheet 8
BT_UART10_RXD: R696.2 ; also on sheet 8
BT_UART10_TXD: U43.4(A2) ; also on sheet 8
BT_UART_CTS_1V8: R681.1 U44.5(A3)
BT_UART_RTS_1V8: R682.1 U43.19(B3)
BT_UART_RXD_1V8: R678.1 U44.4(A2)
BT_UART_TXD_1V8: R680.1 U43.20(B2)
BT_WAKE_B_3V3: R677.1 ; also on sheet 8
CAN1_H: C273.2 D21.2(CATHODE2) FL1.1 J34.1 R649.2 R650.1
CAN1_L: C275.1 D21.1(CATHODE1) FL1.2 J34.3 R651.2 R652.2
CAN1_RX: U41.4(RXD) ; also on sheet 8
CAN1_TX: U41.1(TXD) ; also on sheet 8
CAN3_H: C279.2 D22.2(CATHODE2) FL2.1 J35.1 R658.2 R659.1
CAN3_L: C281.1 D22.1(CATHODE1) FL2.2 J35.3 R660.2 R661.2
CAN3_RX: U42.4(RXD) ; also on sheet 8
CAN3_TX: U42.1(TXD) ; also on sheet 8
CAN_STBY: R647.1 R656.1 ; also on sheet 8
COEX1: J36.48(COEX1) J108.3
COEX2: J36.46(COEX2) J108.4
COEX3: J36.44(COEX3) J108.5
DBGIF_ISP1_CTRL: R2107.2 U362.2(A) ; also on sheet 23
DBGIF_ISP2_CTRL: R2109.2 U365.2(A) ; also on sheet 23
DBGIF_ISP3_CTRL: R2111.2 U366.2(A) ; also on sheet 23
EWM_OUT_B: C569.1 R2101.2 U361.9(I) ; also on sheet 5 8
Flash_RST: C573.1 R2104.2 U361.13(I) ; also on sheet 8
FLASH_VCC: R2103.1 ; also on sheet 6 8 11
GPIO_AON_00: R708.2 ; also on sheet 8
GPIO_AON_01: R710.2 ; also on sheet 8
GPIO_AON_02: R712.2 ; also on sheet 8
I2C2_SCL_1V8: R689.1 R694.2 U126.4(A2)
I2C2_SDA_1V8: R688.1 R692.2 U126.5(A1)
LPI2C2_SCL: R1322.1 ; also on sheet 8 14 26 29
LPI2C2_SDA: R1321.1 ; also on sheet 8 14 26 29
LPSPI6_CLK: R2168.1 ; also on sheet 8
LPSPI6_CS: R2169.1 ; also on sheet 8
LPSPI6_SDI: R2166.1 ; also on sheet 8
LPSPI6_SDO: R2635.1 ; also on sheet 8
OCT_FLASH_RST_B: J93.2 J94.2 R2103.2 ; also on sheet 11
OTG1_DN: L16.2 R623.2 ; also on sheet 9
OTG1_DP: L16.3 R628.2 ; also on sheet 9
OTG2_DN: L19.2 R634.2 R691.1 ; also on sheet 9
OTG2_DP: L19.3 R637.2 R690.1 ; also on sheet 9
POR_CTL: C562.1 R2098.2 U361.1(I) ; also on sheet 5 6
POR_PIN_RST_B: C571.1 J88.2 J89.2 J90.2 J91.2 J92.2 R2102.2 U361.11(I) ; also on sheet 7 27
RST_TGTMCU_B: C565.1 R2099.2 U361.3(I) ; also on sheet 6 26 27
SENSOR_3V3: C272.1 C278.1 C288.1 L33.1 R624.1 R627.1 R629.1 R635.1 R639.1 R640.1 R646.1 R655.1 R1314.1 R1315.1 R1316.1 R2101.1 R2104.1 R2113.1 U41.5(VIO) U42.5(VIO) Y3.3(CLKOE) Y3.4(VDD) ; also on sheet 2 5 6 7 8 9 10 11 12 13 14 15 16 17 18 23 24 25 26 27 28 29 30 31
SPI_FRM_1V8: J36.64(RESERVED) R2169.2
SPI_RXD_1V8: J36.40(VEN_DEF2) J108.2 R2166.2 U43.14(B8)
SPI_TXD_1V8: J36.38(VEN_DEF1) J108.1 R2635.2
TRG_RST: C567.1 R2100.2 U361.5(I) ; also on sheet 23
USB_OTG1_ID: Q11.2(GATE) R629.2 R632.2 ; also on sheet 8
USB_OTG1_OC: R625.1 ; also on sheet 8
USB_OTG1_PWR: R630.1 ; also on sheet 8
USB_OTG2_ID: Q12.2(GATE) R640.2 R643.2 ; also on sheet 8
USB_OTG2_OC: R636.1 ; also on sheet 8
USB_OTG2_PWR: R641.1 ; also on sheet 8
V_TGTMCU: R2099.1 R2100.1 ; also on sheet 23
WIFI_LED1_B: D23.C(CATHODE) J36.6(~{LED1})
WIFI_RST_B: U43.3(A1) ; also on sheet 8
WIFI_RST_B_1V8: R676.1 U43.21(B1)
WIFI_SDIO_CLK: R668.1 ; also on sheet 10
WIFI_SDIO_CMD: R670.1 ; also on sheet 10
WIFI_SDIO_D0: R671.1 ; also on sheet 10
WIFI_SDIO_D1: R672.1 ; also on sheet 10
WIFI_SDIO_D2: R673.1 ; also on sheet 10
WIFI_SDIO_D3: R674.1 ; also on sheet 10
WIFI_WAKE_B_1V8: R675.1 U44.3(A1)
WIFI_WAKE_B_3V3: J105.2 ; also on sheet 8
WL_3V3: C283.1 C284.1 C285.1 C287.1 C289.1 C292.1 C525.1 J36.2(3V3_1) J36.4(3V3_2) J36.72(3V3_3) J36.74(3V3_4) L33.2 R662.1 R665.1 R666.2 R667.2 R705.1 R1323.1 R1324.1 U43.1(VCCA) U44.23(VCCB1) U44.24(VCCB2) U126.7(VCCB)
WL_DEV_WAKE: U43.10(A8) ; also on sheet 8
WL_RST#: R664.1 ; also on sheet 8
N99833017: J33.1(VBUS) L15.1 U38.6(VBUS)
N99833038: J33.2(D-) L16.1 R623.1 U38.1(DM)
N99833048: J33.3(D+) L16.4 R628.1 U38.2(DP)
N99833086: J33.4(ID) R632.1 U38.3(USB_ID)
N100168474: C263.1 C264.1 R622.2 U37.B1(VINT1) U37.B2(VINT2) U37.C1(VINT3)
N100169105: Q11.3(DRAIN) R627.2 R630.2 R631.1 U37.A1(EN)
N100169932: J68.1(VBUS) L18.1 U40.6(VBUS)
N100169943: J68.2(D-) L19.1 R634.1 U40.1(DM)
N100169951: J68.3(D+) L19.4 R637.1 U40.2(DP)
N100169961: J68.4(ID) R643.1 U40.3(USB_ID)
N100171083: R635.2 R636.2 U39.A2(~{FAULT})
N100171101: C267.1 C268.1 R633.2 U39.B1(VINT1) U39.B2(VINT2) U39.C1(VINT3)
N100171150: Q12.3(DRAIN) R639.2 R641.2 R642.1 U39.A1(EN)
N100171345: R638.1 U39.A3(ILIM)
N100797217: R646.2 R647.2 R648.1 U41.8(S)
N100797464: FL1.4 R649.1 U41.7(CANH)
N100797616: FL1.3 R652.1 U41.6(CANL)
N100798376: C274.1 R650.2 R651.1
N101142474: R624.2 R625.2 U37.A2(~{FAULT})
N101142476: R626.1 U37.A3(ILIM)
N101241745: C270.1 C271.1 R644.2 U41.3(VCC)
N101733751: D23.A(ANODE) R666.1
N101733753: D24.A(ANODE) R667.1
N101733765: J36.50(SUSCLK) R686.2
N101733775: L21.2 R690.2
N101733777: L21.3 R691.2
N101733827: J36.5(USB_D-) L21.4
N101733829: J36.3(USB_D+) L21.1
N101733917: J36.58(I2C_DATA) R688.2
N101733919: J36.60(I2C_CLK) R689.2
N101734031: C282.1 R662.2 R663.1 R664.2
N101734037: J36.56(~{W_DISABLE1}) R663.2
N101734088: R705.2 U43.2(DIR)
N101734122: C286.1 R665.2 R669.2 R679.1
N101734218: J36.54(~{W_DISABLE2}) R679.2
N101734224: J36.23(~{SDIO_RST}) R676.2
N101734331: J36.9(SDIO_CLK) R668.2
N101734351: J36.11(SDIO_CMD) R670.2
N101734355: J36.13(SDIO_DATA0) R671.2
N101734367: J36.15(SDIO_DATA1) R672.2
N101734379: J36.17(SDIO_DATA2) R673.2
N101734391: J36.19(SDIO_DATA3) R674.2
N101734410: J36.21(~{SDIO_WAKE}) R675.2
N101734451: J36.36(UART_RTS) R682.2
N101734453: J36.34(UART_CTS) R681.2
N101734459: J36.32(UART_TXD) R680.2
N101734471: J36.22(UART_RXD) R678.2
N101734503: J36.20(~{UART_WAKE}) R677.2
N101734640: J36.10(I2S_WS) R684.2
N101734642: J36.12(I2S_SD_IN) R685.2
N101734644: J36.8(I2S_SCK) R683.2
N101734654: J36.14(I2S_SD_OUT) R687.2
N101736970: R706.2 U44.2(DIR)
N101753271: J78.1 U43.17(B5)
N101753274: J79.1 U43.16(B6)
N101754296: R701.2 U44.7(A5)
N101754314: R703.2 U44.8(A6)
N101754512: J80.1 U44.17(B5)
N101754515: J81.1 U44.16(B6)
N102898927: R696.1 U44.20(B2)
N102898934: R697.1 U44.19(B3)
N102898941: R699.1 U44.18(B4)
N103179532: C526.1 J33.6(SHELL1) J33.7(SHELL2) J33.8(SHELL3) J33.9(SHELL4) R1325.1
N103179921: C527.1 J68.6(SHELL1) J68.7(SHELL2) J68.8(SHELL3) J68.9(SHELL4) R1326.1
N103602996: R655.2 R656.2 R657.1 U42.8(S)
N103603009: FL2.4 R658.1 U42.7(CANH)
N103603017: FL2.3 R661.1 U42.6(CANL)
N103603047: C280.1 R659.2 R660.1
N104315925: C276.1 C277.1 R653.2 U42.3(VCC)
N105488843: R686.1 Y3.1(CLKOUT)
N105851215: R1321.2 R1324.2 U126.8(B1)
N105851217: R1322.2 R1323.2 U126.1(B2)
N105851251: R1320.2 U126.6(OE)
N105870078: R1316.2 SW5.5(B4)
N105870081: R1315.2 SW5.6(B3)
N105870084: R1314.2 SW5.7(B2)
N106191377: J102.1 U362.4(Y)
N106191386: J104.1 U366.4(Y)
N106191553: J103.1 U365.4(Y)
N106192914: C578.1 R1900.1 R2113.2 U356.3(VCC)
N106192924: C577.1 J92.1 R1900.2 R2090.2 U356.2(~{RESET})
N106193141: J90.1 U361.2(O)
N106193157: J91.1 U361.6(O)
N106193171: J93.1 U361.10(O)
N106193408: J94.1 U361.12(O)
N106193418: J88.1 U361.4(O)
N106193455: J89.1 U361.8(O)
N106641917: J105.1 U44.21(B1)

Not connected (* = marked no-connect by the designer): J36 35(PET_P0)* 37(PET_N0)* 41(PER_P0)* 43(PER_N0)* 47(REFCLK_P0)* 49(REFCLK_N0)* 52(~{PERST0})* 53(~{CLKREQ0})* 55(~{PEWAKE0})* 59(PET_P1)* 61(PET_N1)* 62(~{ALERT})* 65(PER_P1)* 66(~{PERST1})* 67(PER_N1)* 68(~{CLKREQ1})* 70(~{PEWAKE1})* 71(REFCLK_P1)* 73(REFCLK_N1)*; SW5 1(A1)* 8(B1)*; U38 4(NC1)* 5(NC2)*; U40 4(NC1)* 5(NC2)*; U44 9(A7)* 10(A8)* 14(B8)* 15(B7)*; U362 1(NC)*; U365 1(NC)*; U366 1(NC)*

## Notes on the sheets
sheet 19
- USB OTG1
- USB1 Power
- MAX 500 mA @5V
- 90ohm differential pairs
- USB ID is a processor Analog Sense Input
  Host --> ID = GND
  Device --> ID = Floating
- USB OTG2
- USB2 Power
- MAX 500 mA @5V
- 90ohm differential pairs
- USB ID is a processor Analog Sense Input
  Host --> ID = GND
  Device --> ID = Floating
sheet 20
- CAN1  Bus
- MAX 70 mA @5V
- CAN3  Bus
- MAX 70 mA @5V
sheet 21
- Compatible with  M.2 Modules
- To apply M.2 based card, need put on J5
  to switch SDIO singals as 1.8V
- 1V8 CPU OUT
- 1V8 CPU IN/OUT
- 1V8 CPU IN/OUT
- 1V8 CPU IN/OUT
- 1V8 CPU IN/OUT
- 1V8 CPU IN/OUT
- 1V8 CPU IN
- 3V3 CPU OUT
- 1V8 CPU OUT
- 3V3 CPU OUT
- LED IN/OD
- 3V3 CPU IN
- 3V3 CPU OUT
- LED IN/OD
- 1V8 CPU IN
- 1V8 CPU OUT
- 1V8 CPU IN
- 1V8 CPU OUT
- 1V8 CPU IN/OUT
- 1V8 CPU IN
- 1V8 CPU IN/OUT
- 1V8 CPU OUT
- 1V8 CPU IN/OUT
- 1V8 CPU OUT
- Layout Note：Minimize These Stubs
- 90ohm differential pairs
- Stand-off for M.2
- Default: 1-2
- Default: open
- Default: open
- Default: open
- Default: 1-2
- DIR=H, A=INPUT, B=OUTPUT
- DIR=H, A=INPUT, B=OUTPUT
sheet 22
- External Boot Switch
- Boot Mode pin settings
- BOOT_MODE[2:0]
- Boot Type
- 000(SW5-x000)
- Boot from Internal Fuses
- 001(SW5-x001)
- Serial Downloader (USB1 or LPUART1)
- 010(SW5-x010)
- USDHC2 8-bit 1.8V eMMC 5.1
- 011(SW5-x011)
- uSDHC1 4-bit SD 3.0
- 100(SW5-x100)
- FlexSPI Quad SPI Serial NOR
   (or Octal SPI NOR in Quad SPI NOR mode)
- 101(SW5-x101)
- FlexSPI Quad SPI Serial NAND 2k page
  (or Octal SPI NAND in Quad SPI NOR mode)
- On-chip defaults:
  BOOTMODE[2:0] =  25-50 kohm PD
- 110(SW5-x110)
- FlexSPI Quad SPI Serial NAND 4k page
  (or Octal SPI NAND in Quad SPI NOR mode)
- 111(SW5-x111)
- Test Mode
- Layout Note：Minimize These Stubs
- System Reset Logic
- Optional External Reset Circuit
- POR_B PIN RESET
- # Open
  Drain
- Default: Open
- RESET to OCTFLASH
- PWR_on_Reset
- MCU-link_RESET
- Default: 1-2
- Default: 1-2
- Default: 1-2
- Reset Button
- Flash_RST CTL
- Watchdog_RESET
- Default: Open
- Default: Open
- Default: Open
- ISP Control for Factory Automation
- Note: If ISP Automatic Control  is used,
  You need to configure SW5 to be x111 first
- Default: Open
- Default: Open
- Default: Open
